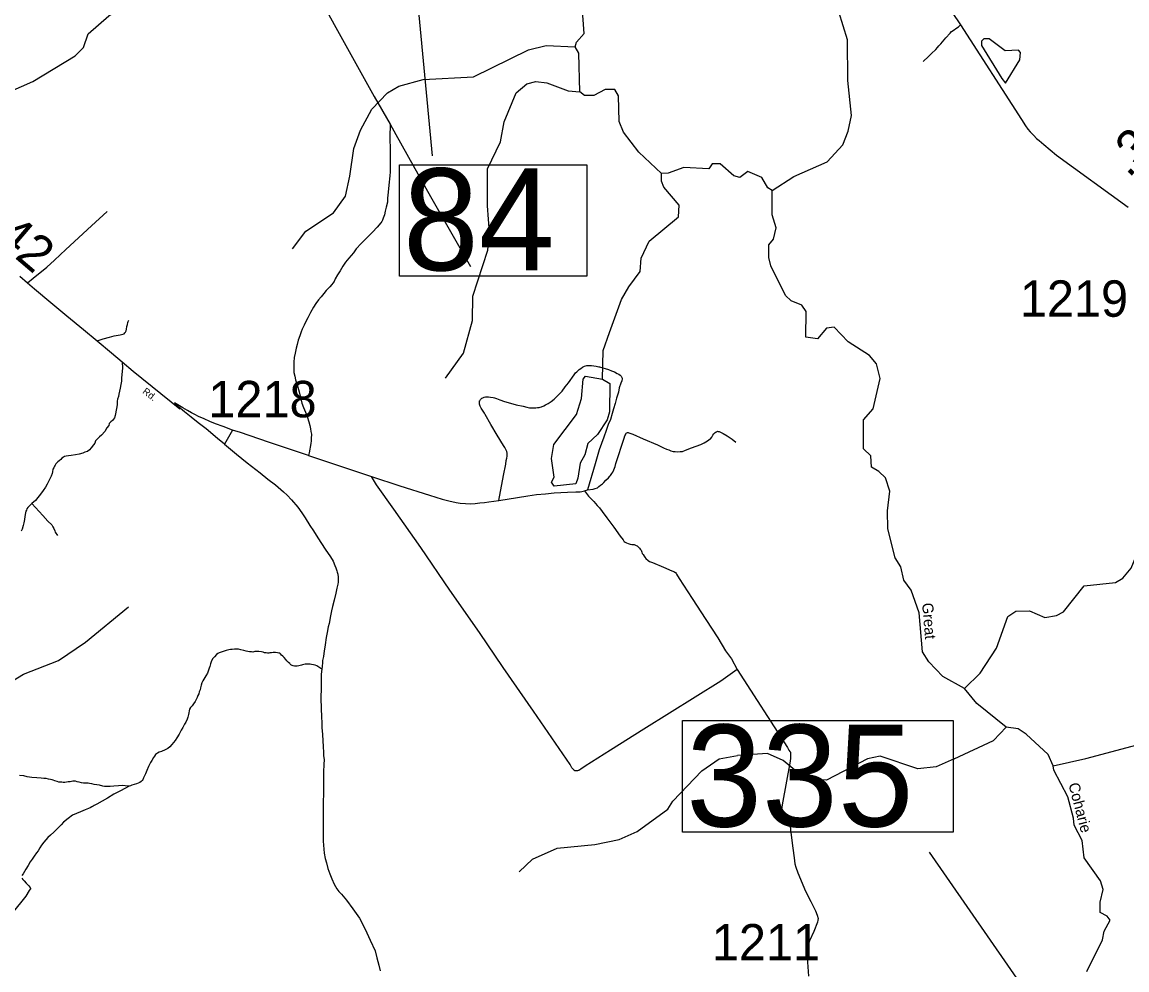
# Model space of a CAD drawing. Extents: x 2093524 to 2270757, y 289120 to 570408.
# Drawn here: x 2177691 to 2192870, y 409015 to 422036 of the extents above; entities that cross this region are included whole.
import ezdxf

# ---------------------------------------------------------------- set-up
doc = ezdxf.new("R2010")
doc.units = 0
for name, color, linetype in [('Exist Hydrographic Creek Single Shore', 7, 'Continuous'), ('Exist Hydrographic Creek Single Shore Label', 7, 'Continuous'), ('Exist Hydrographic Misc Water Feature', 7, 'Continuous'), ('Exist Hydrographic Pond Under 1500 Sq Ft', 7, 'Continuous'), ('Exist Road Non-System Type 51', 7, 'Continuous'), ('Exist Road Secondary Mileage Hundredths English Label', 7, 'Continuous'), ('Exist Road Secondary Structure Standard Bridge Number Label', 7, 'Continuous'), ('Exist Road Secondary Type 51 Attributed', 7, 'Continuous'), ('Exist Road Secondary Type 51 Label', 7, 'Continuous'), ('Exist Road Secondary Type 51 Number Label', 7, 'Continuous')]:
    doc.layers.add(name, color=color, linetype=linetype)

msp = doc.modelspace()

# ---------------------------------------------------------------- linework, layer by layer
at = {"layer": 'Exist Hydrographic Creek Single Shore'}
for p, q in [((2190641, 412882), (2190856, 413090)), ((2191857, 411818), (2192306, 411920))]:
    msp.add_line(p, q, dxfattribs=at)
for points in [[(2185290, 421694), (2185306, 421759), (2185414, 421878), (2185387, 422253), (2185336, 422359), (2185111, 422393), (2185069, 422433), (2185061, 422515), (2184967, 422799), (2184825, 422973), (2184707, 423182), (2184665, 423205), (2184440, 423197), (2184340, 423254), (2184302, 423269), (2184287, 423294), (2184287, 423336), (2184298, 423396), (2184316, 423557), (2184309, 423637)], [(2185352, 421076), (2185341, 421611), (2185290, 421694)], [(2186475, 419958), (2186165, 420249), (2185955, 420523), (2185896, 420671), (2185885, 421023), (2185835, 421112), (2185702, 421112), (2185544, 421029), (2185419, 421029), (2185352, 421076)], [(2187471, 419925), (2187282, 420089), (2187174, 420088), (2187124, 420020), (2186782, 420037), (2186566, 419959), (2186475, 419958)], [(2187995, 419721), (2187937, 419761), (2187852, 419901), (2187660, 419983), (2187552, 419900), (2187471, 419925)], [(2188459, 417708), (2188465, 418058), (2188406, 418148), (2188256, 418207), (2188180, 418281), (2187977, 418688), (2187952, 418803), (2187950, 418977), (2188016, 419055), (2188049, 419211), (2187997, 419386), (2187995, 419721)], [(2190641, 412882), (2190340, 413048), (2190147, 413246), (2190063, 413385), (2190018, 413921), (2189907, 414234), (2189806, 414368), (2189764, 414552), (2189688, 414675), (2189585, 415074), (2189583, 415323), (2189615, 415592), (2189555, 415773), (2189463, 415864), (2189363, 415921), (2189353, 416079), (2189253, 416173), (2189250, 416570), (2189382, 416721), (2189479, 417139), (2189428, 417341), (2189335, 417454), (2189042, 417643), (2188849, 417844), (2188741, 417833), (2188618, 417686), (2188459, 417708)], [(2190856, 413090), (2191079, 413434), (2191234, 413870), (2191342, 413943), (2191534, 413946), (2191743, 413857), (2191901, 413883), (2192000, 413934), (2192281, 414292), (2192714, 414339), (2192813, 414396), (2192929, 414532), (2192995, 414691), (2193164, 415475)], [(2192306, 411920), (2193012, 412106), (2193421, 412111), (2194196, 412033), (2195511, 412092), (2195603, 412058), (2195886, 412111), (2196410, 412281), (2196634, 412398), (2197197, 412879), (2198055, 414118)], [(2191211, 412352), (2190809, 412675), (2190641, 412882)], [(2191857, 411818), (2191789, 411973), (2191487, 412255), (2191378, 412329), (2191211, 412352)], [(2192545, 410121), (2192509, 410237), (2192282, 410553), (2192255, 410793), (2192146, 411002), (2192136, 411100), (2192059, 411394), (2191865, 411758), (2191857, 411818)], [(2192319, 408994), (2192533, 409429), (2192557, 409547), (2192639, 409696), (2192597, 409753), (2192505, 409804), (2192505, 409945), (2192545, 410121)]]:
    msp.add_lwpolyline(points, dxfattribs=at)
at = {"layer": 'Exist Hydrographic Misc Water Feature'}
msp.add_line((2187995, 419721), (2188294, 419915), dxfattribs=at)
for points in [[(2188294, 419915), (2188750, 420116), (2188965, 420351), (2189039, 420537), (2189088, 420752), (2189034, 421235), (2189030, 421793), (2188852, 422374), (2188808, 422624), (2188814, 422906), (2188913, 423157), (2189325, 423729), (2189358, 423827), (2189311, 424553), (2189510, 424703), (2190133, 424933)], [(2177157, 420849), (2177414, 421031), (2177837, 421219), (2178418, 421572), (2178535, 421687), (2178600, 421873), (2178882, 422123), (2179197, 422343), (2179520, 422695), (2180558, 423208), (2180716, 423268), (2180949, 423293), (2181266, 423237), (2181591, 423263), (2181766, 423348), (2182030, 423642), (2182213, 423776), (2182578, 423942), (2182736, 424054), (2183184, 424439)], [(2181407, 418921), (2181589, 419166), (2181971, 419418), (2182136, 419644), (2182193, 419919), (2182249, 420301), (2182339, 420552), (2182496, 420838), (2182711, 421063), (2182869, 421155), (2183202, 421247), (2183893, 421285), (2184649, 421657), (2184890, 421715), (2185290, 421694)], [(2183508, 417144), (2183756, 417486), (2183879, 417937), (2183885, 418271), (2184090, 418903), (2184113, 419146), (2184086, 419514), (2184084, 420022), (2184265, 420389), (2184313, 420664), (2184477, 421064), (2184627, 421189), (2184751, 421222), (2184901, 421200), (2185193, 421092), (2185352, 421076)], [(2186719, 419520), (2186509, 419767), (2186475, 419850), (2186475, 419958)], [(2185666, 417130), (2185672, 417524), (2185762, 417771), (2185926, 418224), (2186025, 418399), (2186182, 418609), (2186198, 418792), (2186305, 419026), (2186711, 419360), (2186719, 419520)], [(2175727, 410020), (2175724, 410519), (2175805, 410809), (2176035, 411395), (2176135, 411488), (2176434, 411662), (2176632, 411924), (2177012, 412559), (2177377, 412877), (2177709, 413080), (2178191, 413264), (2178564, 413516), (2179153, 414003)], [(2190498, 411913), (2191038, 412168), (2191211, 412352)], [(2190498, 411913), (2190249, 411804), (2189999, 411779), (2189482, 411950), (2189307, 411914), (2188742, 411620), (2188509, 411642), (2188359, 411717), (2188149, 411891), (2187932, 411988), (2187519, 411960)], [(2184521, 410360), (2184704, 410536), (2185044, 410687), (2185560, 410739), (2185893, 410808), (2186142, 410918), (2186565, 411221), (2186632, 411331), (2187029, 411750), (2187270, 411915), (2187519, 411960)]]:
    msp.add_lwpolyline(points, dxfattribs=at)
at = {"layer": 'Exist Hydrographic Pond Under 1500 Sq Ft'}
for points in [[(2191200, 421199), (2191398, 421516), (2191406, 421618), (2191380, 421651), (2191197, 421642), (2190979, 421807), (2190905, 421805), (2190872, 421773), (2190872, 421714), (2191150, 421259), (2191200, 421199)], [(2185666, 417130), (2185766, 417072), (2185760, 416682), (2185727, 416571), (2185595, 416371), (2185463, 416245), (2185422, 416089), (2185356, 415978), (2185324, 415769), (2185299, 415694), (2184999, 415661), (2184966, 415717), (2184999, 415785), (2184964, 416042), (2184996, 416235), (2185310, 416645), (2185376, 416864), (2185399, 417129), (2185432, 417171), (2185666, 417130)]]:
    msp.add_lwpolyline(points, dxfattribs=at)
at = {"layer": 'Exist Road Non-System Type 51'}
for p, q in [((2180583, 416432), (2180472, 416239)), ((2181624, 416084), (2182489, 415795)), ((2185418, 415595), (2185460, 415608))]:
    msp.add_line(p, q, dxfattribs=at)
for points in [[(2180290, 425031), (2180357, 424909), (2181399, 423046), (2182528, 421015), (2182748, 420636)], [(2190073, 421496), (2190145, 421565), (2190186, 421603), (2190244, 421659), (2190268, 421686), (2190288, 421710), (2190315, 421736), (2190381, 421818), (2190440, 421883), (2190462, 421905), (2190484, 421921), (2190534, 421957), (2190556, 421970), (2190586, 421999)], [(2182748, 420636), (2182745, 420456), (2182748, 420273), (2182749, 420057), (2182748, 419981), (2182742, 419925), (2182731, 419795), (2182721, 419699), (2182712, 419617), (2182710, 419561), (2182695, 419495), (2182681, 419439), (2182669, 419387), (2182653, 419344), (2182642, 419316), (2182634, 419298), (2182618, 419278), (2182570, 419220), (2182503, 419152), (2182351, 418993), (2182282, 418920), (2182242, 418868), (2182181, 418794), (2182133, 418738), (2182097, 418684), (2182062, 418621), (2182024, 418563), (2181994, 418511), (2181977, 418473), (2181961, 418451), (2181945, 418429), (2181919, 418399), (2181869, 418348), (2181836, 418308), (2181800, 418264), (2181762, 418220), (2181727, 418168), (2181695, 418120), (2181651, 418047), (2181615, 417975), (2181586, 417915), (2181568, 417873), (2181540, 417819), (2181527, 417779), (2181507, 417724), (2181483, 417666), (2181470, 417606), (2181458, 417558), (2181442, 417488), (2181431, 417426), (2181423, 417366), (2181423, 417320), (2181423, 417282), (2181426, 417222), (2181438, 417174), (2181449, 417122), (2181479, 417019), (2181497, 416955), (2181516, 416879), (2181536, 416801), (2181557, 416741), (2181583, 416677), (2181607, 416616), (2181628, 416546), (2181642, 416496), (2181654, 416450), (2181656, 416412), (2181665, 416376), (2181665, 416360), (2181663, 416330), (2181663, 416284), (2181657, 416248), (2181650, 416198), (2181646, 416170), (2181634, 416120), (2181624, 416084)], [(2182748, 420636), (2182827, 420491), (2183302, 419642), (2183851, 418679)], [(2177766, 418455), (2177844, 418517), (2178031, 418669), (2178136, 418765), (2178291, 418910), (2178643, 419236), (2178860, 419435)], [(2178722, 417655), (2178806, 417685), (2178890, 417706), (2178956, 417724), (2179038, 417739), (2179074, 417747), (2179092, 417753), (2179102, 417767), (2179112, 417777), (2179119, 417793), (2179125, 417819), (2179131, 417855), (2179137, 417881), (2179145, 417907), (2179149, 417925), (2179159, 417943)], [(2179066, 417371), (2179068, 417281), (2179063, 417193), (2179057, 417145), (2179056, 417103), (2179048, 417059), (2179040, 417007), (2179030, 416965), (2179020, 416923), (2179013, 416893), (2179003, 416855), (2178997, 416829), (2178999, 416779), (2178990, 416727), (2178968, 416631), (2178958, 416601), (2178946, 416580), (2178931, 416562), (2178909, 416544), (2178889, 416520), (2178881, 416496), (2178857, 416462), (2178826, 416410), (2178782, 416362), (2178756, 416338), (2178730, 416315), (2178716, 416301), (2178700, 416283), (2178688, 416253), (2178673, 416227), (2178639, 416187), (2178615, 416159), (2178589, 416139), (2178553, 416126), (2178525, 416114), (2178475, 416102), (2178423, 416092), (2178365, 416083), (2178330, 416079), (2178294, 416073), (2178274, 416067), (2178258, 416061), (2178238, 416047), (2178224, 416027), (2178200, 416010), (2178180, 415993), (2178164, 415978), (2178154, 415966), (2178144, 415950), (2178134, 415936), (2178125, 415914), (2178115, 415892), (2178109, 415856), (2178103, 415834), (2178089, 415800), (2178077, 415772), (2178056, 415734), (2178034, 415688), (2178012, 415646), (2177982, 415600), (2177945, 415549), (2177907, 415505), (2177873, 415465), (2177823, 415421)], [(2184243, 415465), (2184305, 415805), (2184336, 415965), (2184343, 416013), (2184349, 416045), (2184353, 416075), (2184353, 416093), (2184355, 416115), (2184351, 416139), (2184341, 416157), (2184333, 416175), (2184322, 416193), (2184307, 416219), (2184220, 416363), (2184133, 416506), (2184054, 416643), (2184042, 416665), (2183998, 416733), (2183983, 416761), (2183975, 416785), (2183973, 416795), (2183975, 416811), (2183975, 416823), (2183977, 416829), (2183977, 416831), (2183979, 416835), (2183983, 416843), (2183989, 416851), (2183995, 416857), (2184001, 416863), (2184009, 416869), (2184019, 416875), (2184029, 416881), (2184041, 416885), (2184057, 416887), (2184071, 416889), (2184085, 416887), (2184101, 416887), (2184127, 416884), (2184161, 416880), (2184183, 416874), (2184207, 416864), (2184255, 416846), (2184317, 416825), (2184401, 416801), (2184477, 416780), (2184573, 416758), (2184627, 416745), (2184663, 416739), (2184693, 416735), (2184728, 416735), (2184751, 416735), (2184773, 416740), (2184793, 416741), (2184807, 416746), (2184827, 416750), (2184857, 416766), (2184883, 416778), (2184919, 416798), (2184959, 416824), (2185001, 416857), (2185058, 416909), (2185112, 416967), (2185153, 417024), (2185197, 417078), (2185275, 417188), (2185296, 417216), (2185314, 417232), (2185344, 417262), (2185366, 417278), (2185390, 417297), (2185418, 417309), (2185450, 417317), (2185482, 417317), (2185512, 417319), (2185548, 417314), (2185576, 417308), (2185614, 417302), (2185624, 417300), (2185670, 417288), (2185704, 417279), (2185748, 417265), (2185788, 417247), (2185828, 417231), (2185866, 417209), (2185888, 417198), (2185908, 417184), (2185920, 417170), (2185926, 417162), (2185935, 417146), (2185935, 417134), (2185929, 417108), (2185919, 417074), (2185896, 417010), (2185884, 416950), (2185858, 416871), (2185837, 416797), (2185817, 416721), (2185797, 416659), (2185774, 416577)], [(2180583, 416432), (2180453, 416479), (2180346, 416518), (2180272, 416550), (2180190, 416584), (2180116, 416617), (2180062, 416645), (2180019, 416669), (2179965, 416700), (2179897, 416738), (2179783, 416805)], [(2180472, 416239), (2180377, 416315), (2180221, 416446), (2180110, 416531), (2180012, 416608), (2179924, 416682), (2179845, 416744), (2179783, 416805)], [(2185774, 416577), (2185744, 416507), (2185717, 416427), (2185683, 416333), (2185620, 416162), (2185563, 415966), (2185460, 415608)], [(2181624, 416084), (2181074, 416264), (2180693, 416400), (2180583, 416432)], [(2185460, 415608), (2185538, 415620), (2185565, 415628), (2185595, 415640), (2185617, 415657), (2185639, 415673), (2185667, 415693), (2185685, 415713), (2185711, 415743), (2185748, 415777), (2185768, 415799), (2185776, 415809), (2185784, 415822), (2185792, 415836), (2185806, 415854), (2185820, 415884), (2185838, 415932), (2185849, 415970), (2185881, 416068), (2185930, 416226), (2185963, 416322), (2185973, 416352), (2185981, 416366), (2185985, 416378), (2185991, 416387), (2186001, 416393), (2186007, 416396), (2186011, 416397), (2186017, 416397), (2186027, 416395), (2186039, 416389), (2186083, 416373), (2186223, 416310), (2186420, 416227), (2186504, 416189), (2186546, 416168), (2186576, 416158), (2186602, 416148), (2186634, 416138), (2186664, 416136), (2186692, 416134), (2186732, 416137), (2186764, 416139), (2186806, 416153), (2186886, 416188), (2187015, 416234), (2187063, 416257), (2187107, 416283), (2187127, 416299), (2187145, 416311), (2187147, 416313), (2187167, 416335), (2187182, 416359), (2187194, 416379), (2187214, 416397), (2187226, 416408), (2187234, 416409), (2187240, 416413), (2187244, 416415), (2187256, 416413), (2187266, 416412), (2187278, 416408), (2187324, 416384), (2187380, 416352), (2187447, 416307), (2187495, 416267)], [(2180472, 416239), (2180635, 416100), (2180785, 415981), (2180962, 415842), (2181066, 415759), (2181171, 415679), (2181283, 415582), (2181332, 415536), (2181394, 415471), (2181480, 415371), (2181535, 415296), (2181579, 415224), (2181646, 415118), (2181694, 415045), (2181755, 414949), (2181853, 414794), (2181926, 414688), (2181964, 414628), (2181989, 414570), (2182001, 414537), (2182013, 414499), (2182019, 414479), (2182027, 414451), (2182031, 414443), (2182034, 414419), (2182034, 414385), (2182034, 414363), (2182032, 414341), (2182028, 414313), (2182014, 414261), (2181999, 414191), (2181979, 414095), (2181956, 414007), (2181942, 413950), (2181929, 413880), (2181909, 413776), (2181898, 413730), (2181884, 413652), (2181870, 413580), (2181855, 413482), (2181853, 413474), (2181841, 413398), (2181830, 413320), (2181820, 413266), (2181816, 413240), (2181812, 413182), (2181809, 413148)], [(2182489, 415795), (2182882, 415667), (2183287, 415535), (2183375, 415508), (2183463, 415482), (2183553, 415457), (2183655, 415438), (2183709, 415426), (2183783, 415422), (2183845, 415419), (2183917, 415421), (2183981, 415431), (2184045, 415434), (2184105, 415444), (2184173, 415455), (2184243, 415465)], [(2187514, 413144), (2187290, 412981), (2186234, 412323), (2185774, 412033), (2185429, 411813), (2185369, 411771), (2185355, 411763), (2185341, 411756), (2185331, 411754), (2185321, 411750), (2185310, 411750), (2185297, 411748), (2185287, 411752), (2185273, 411758), (2185265, 411768), (2185253, 411782), (2185245, 411792), (2185219, 411836), (2184717, 412571), (2184302, 413168), (2183973, 413648), (2183568, 414234), (2183167, 414817), (2182800, 415345), (2182558, 415681), (2182489, 415795)], [(2184243, 415465), (2184496, 415506), (2184640, 415527), (2184760, 415548), (2184884, 415556), (2185002, 415567), (2185184, 415578), (2185300, 415581), (2185356, 415583), (2185382, 415589), (2185398, 415591), (2185418, 415595)], [(2185418, 415595), (2185472, 415524), (2185546, 415448), (2185593, 415397), (2185625, 415363), (2185659, 415313), (2185724, 415227), (2185822, 415096), (2185909, 414972), (2185947, 414923), (2185953, 414915), (2185959, 414905), (2185965, 414901), (2185975, 414893), (2185997, 414883), (2186017, 414873), (2186043, 414865), (2186068, 414861), (2186098, 414858), (2186111, 414854), (2186128, 414846), (2186142, 414840), (2186152, 414834), (2186162, 414820), (2186174, 414808), (2186184, 414796), (2186196, 414780), (2186206, 414754), (2186212, 414736), (2186224, 414721), (2186236, 414698), (2186248, 414685), (2186262, 414667), (2186291, 414639), (2186313, 414627), (2186353, 414611), (2186501, 414546), (2186619, 414497), (2186643, 414487), (2186658, 414479), (2186667, 414473), (2186676, 414463), (2186682, 414451), (2186718, 414393), (2186897, 414116), (2187087, 413829), (2187248, 413575), (2187355, 413397), (2187436, 413288), (2187514, 413144)], [(2177823, 415421), (2177798, 415397), (2177782, 415380), (2177768, 415366), (2177758, 415350), (2177750, 415330), (2177744, 415318), (2177738, 415292), (2177730, 415244), (2177725, 415204), (2177715, 415158), (2177707, 415120), (2177691, 415072), (2177677, 415044)], [(2177823, 415421), (2177976, 415256), (2178045, 415180), (2178099, 415128), (2178111, 415104), (2178127, 415080), (2178139, 415049), (2178144, 415030), (2178176, 414985)], [(2181809, 413148), (2181767, 413174), (2181741, 413191), (2181716, 413203), (2181693, 413207), (2181668, 413211), (2181648, 413215), (2181627, 413217), (2181609, 413217), (2181594, 413217), (2181581, 413215), (2181560, 413210), (2181545, 413205), (2181529, 413203), (2181511, 413198), (2181493, 413194), (2181471, 413190), (2181433, 413190), (2181417, 413192), (2181401, 413196), (2181385, 413205), (2181373, 413214), (2181367, 413223), (2181352, 413237), (2181330, 413261), (2181314, 413279), (2181290, 413305), (2181274, 413323), (2181256, 413341), (2181242, 413357), (2181230, 413365), (2181220, 413368), (2181198, 413372), (2181172, 413374), (2181152, 413374), (2181138, 413374), (2181116, 413370), (2181096, 413370), (2181080, 413368), (2181064, 413368), (2181044, 413370), (2181022, 413373), (2181002, 413379), (2180982, 413385), (2180944, 413387), (2180920, 413387), (2180890, 413387), (2180862, 413382), (2180844, 413384), (2180816, 413386), (2180792, 413388), (2180768, 413392), (2180736, 413402), (2180698, 413410), (2180666, 413420), (2180638, 413421), (2180610, 413423), (2180578, 413419), (2180554, 413415), (2180530, 413411), (2180496, 413403), (2180466, 413396), (2180428, 413382), (2180398, 413372), (2180378, 413362), (2180362, 413348), (2180336, 413317), (2180312, 413295), (2180295, 413259), (2180277, 413219), (2180269, 413183), (2180263, 413159), (2180251, 413135), (2180248, 413121), (2180238, 413093), (2180216, 413055), (2180202, 413031), (2180188, 413007), (2180172, 412985), (2180160, 412957), (2180151, 412929), (2180143, 412889), (2180135, 412863), (2180125, 412837), (2180117, 412809), (2180107, 412784), (2180096, 412758), (2180084, 412732), (2180068, 412702), (2180046, 412672), (2180026, 412644), (2180006, 412618), (2179992, 412598), (2179987, 412572), (2179981, 412546), (2179975, 412524), (2179967, 412488), (2179957, 412460), (2179942, 412420), (2179922, 412390)], [(2181809, 413148), (2181801, 413078), (2181802, 413028), (2181800, 412900), (2181797, 412738), (2181805, 412486), (2181807, 412416), (2181807, 412346), (2181816, 412249), (2181822, 412160), (2181829, 412083), (2181833, 412002), (2181832, 411962), (2181840, 411899), (2181836, 411841), (2181831, 411733), (2181831, 411611), (2181831, 411435), (2181827, 411325), (2181826, 411187), (2181827, 411065), (2181825, 410945), (2181828, 410847), (2181828, 410785), (2181832, 410727), (2181837, 410675), (2181841, 410619), (2181854, 410547), (2181872, 410485), (2181892, 410407), (2181919, 410336), (2181945, 410264), (2181980, 410192), (2182014, 410128), (2182044, 410090), (2182080, 410054), (2182147, 409975), (2182237, 409853), (2182326, 409726), (2182405, 409574), (2182472, 409425), (2182540, 409277), (2182565, 409179), (2182592, 409079), (2182612, 409002)], [(2187514, 413144), (2188205, 412071), (2188227, 412033), (2188239, 412015), (2188247, 412005), (2188250, 411995), (2188250, 411983), (2188248, 411967), (2188248, 411949), (2188250, 411925), (2188242, 411881), (2188133, 411281), (2188129, 411247), (2188123, 411233), (2188125, 411215), (2188125, 411191), (2188139, 411173), (2188147, 411149), (2188156, 411129), (2188176, 411101), (2188186, 411081), (2188200, 411069), (2188210, 411057), (2188220, 411048), (2188226, 411040), (2188232, 411026), (2188232, 411008), (2188238, 410990), (2188249, 410960), (2188247, 410936), (2188253, 410904), (2188281, 410688), (2188297, 410556), (2188306, 410472), (2188320, 410428), (2188347, 410347), (2188454, 410096), (2188529, 409957), (2188590, 409825), (2188615, 409765), (2188627, 409720), (2188625, 409698), (2188617, 409670), (2188568, 409543), (2188511, 409415), (2188485, 409347), (2188472, 409303), (2188479, 409185), (2188494, 408927)], [(2179922, 412390), (2179900, 412345), (2179878, 412307), (2179849, 412253), (2179815, 412205), (2179793, 412167), (2179769, 412139), (2179750, 412111), (2179722, 412081), (2179692, 412058), (2179658, 412038), (2179606, 412014), (2179574, 412004), (2179550, 411992), (2179524, 411973), (2179509, 411951), (2179494, 411935), (2179473, 411893), (2179457, 411863), (2179429, 411809), (2179406, 411755), (2179384, 411707), (2179358, 411655), (2179343, 411618), (2179336, 411611), (2179328, 411605), (2179308, 411590), (2179263, 411572), (2179229, 411560), (2179199, 411552), (2179181, 411542), (2179161, 411537)], [(2179161, 411537), (2179109, 411543), (2179067, 411547), (2179013, 411543), (2178949, 411538), (2178899, 411534), (2178871, 411536), (2178847, 411536), (2178823, 411536), (2178799, 411541), (2178753, 411551), (2178719, 411559), (2178683, 411563), (2178649, 411571), (2178615, 411577), (2178597, 411579), (2178573, 411580), (2178553, 411580), (2178535, 411580), (2178507, 411586), (2178475, 411592), (2178447, 411600), (2178425, 411608), (2178403, 411607), (2178387, 411609), (2178371, 411603), (2178349, 411601), (2178325, 411597), (2178301, 411595), (2178277, 411590), (2178255, 411591), (2178235, 411592), (2178215, 411592), (2178195, 411596), (2178173, 411604), (2178141, 411612), (2178119, 411620), (2178103, 411625), (2178083, 411631), (2178053, 411637), (2178021, 411643), (2177989, 411643), (2177951, 411647), (2177893, 411654), (2177823, 411660), (2177761, 411668), (2177715, 411679), (2177657, 411687)], [(2179161, 411537), (2179043, 411475), (2178950, 411427), (2178866, 411374), (2178790, 411332), (2178716, 411291), (2178683, 411273), (2178667, 411263), (2178649, 411255), (2178627, 411243), (2178557, 411214), (2178493, 411188), (2178385, 411139), (2178324, 411095), (2178260, 411045), (2178226, 411009), (2178184, 410966), (2178127, 410908), (2178083, 410868), (2178043, 410832), (2177990, 410771), (2177956, 410729), (2177934, 410691), (2177910, 410653), (2177887, 410623), (2177855, 410576), (2177829, 410536), (2177801, 410498), (2177774, 410448), (2177742, 410400), (2177704, 410334), (2177688, 410310)], [(2177689, 410276), (2177701, 410258), (2177717, 410240), (2177747, 410208), (2177783, 410168), (2177797, 410151), (2177801, 410145), (2177803, 410138), (2177805, 410137), (2177805, 410132), (2177804, 410124), (2177803, 410123), (2177790, 410104), (2177740, 410030), (2177555, 409795)]]:
    msp.add_lwpolyline(points, dxfattribs=at)
at = {"layer": 'Exist Road Secondary Structure Standard Bridge Number Label'}
msp.add_line((2182860, 425147), (2183326, 420200), dxfattribs=at)
for points in [[(2182874, 420077), (2185450, 420077), (2185450, 418547), (2182874, 418547)], [(2186765, 412442), (2190481, 412442), (2190481, 410905), (2186765, 410905)]]:
    msp.add_lwpolyline(points, close=True, dxfattribs=at)
msp.add_lwpolyline([(2193084, 405532), (2192592, 407126), (2190158, 410631)], dxfattribs=at)
at = {"layer": 'Exist Road Secondary Type 51 Attributed'}
for points in [[(2189860, 423074), (2190586, 421999), (2191422, 420700), (2191475, 420612), (2191511, 420563), (2191543, 420529), (2191591, 420479), (2191630, 420437), (2191664, 420408), (2191730, 420354), (2191903, 420206), (2192886, 419492)], [(2177658, 418544), (2177766, 418455), (2177861, 418372), (2178086, 418185), (2178307, 418002), (2178536, 417814), (2178722, 417655), (2178917, 417494), (2179066, 417371), (2179217, 417242), (2179860, 416725)]]:
    msp.add_lwpolyline(points, dxfattribs=at)

# ---------------------------------------------------------------- texts
at = {"layer": 'Exist Hydrographic Creek Single Shore Label'}
for s, rotation, p in [('Great', 274.8147, (2190056, 414052)), ('Coharie', 284.7207, (2192065, 411566))]:
    msp.add_text(s, height=150, rotation=rotation, dxfattribs=at).set_placement(p)
at = {"layer": 'Exist Road Secondary Mileage Hundredths English Label'}
for s, rotation, p in [('.36', 45.9449, (2192894, 419883)), ('1.42', 319.6117, (2176868, 419408))]:
    msp.add_text(s, height=500, rotation=rotation, dxfattribs=at).set_placement(p)
at = {"layer": 'Exist Road Secondary Structure Standard Bridge Number Label'}
for s, p in [('84', (2182924, 418626)), ('335', (2186815, 410984))]:
    msp.add_text(s, height=1400, dxfattribs=at).set_placement(p)
at = {"layer": 'Exist Road Secondary Type 51 Label'}
msp.add_text('Rd.', height=95, rotation=322.3429, dxfattribs=at).set_placement((2179337, 416946))
at = {"layer": 'Exist Road Secondary Type 51 Number Label'}
for s, p in [('1219', (2191399, 417988)), ('1218', (2180250, 416607)), ('1211', (2187167, 409145))]:
    msp.add_text(s, height=500, dxfattribs=at).set_placement(p)

doc.saveas('drawing.dxf')
